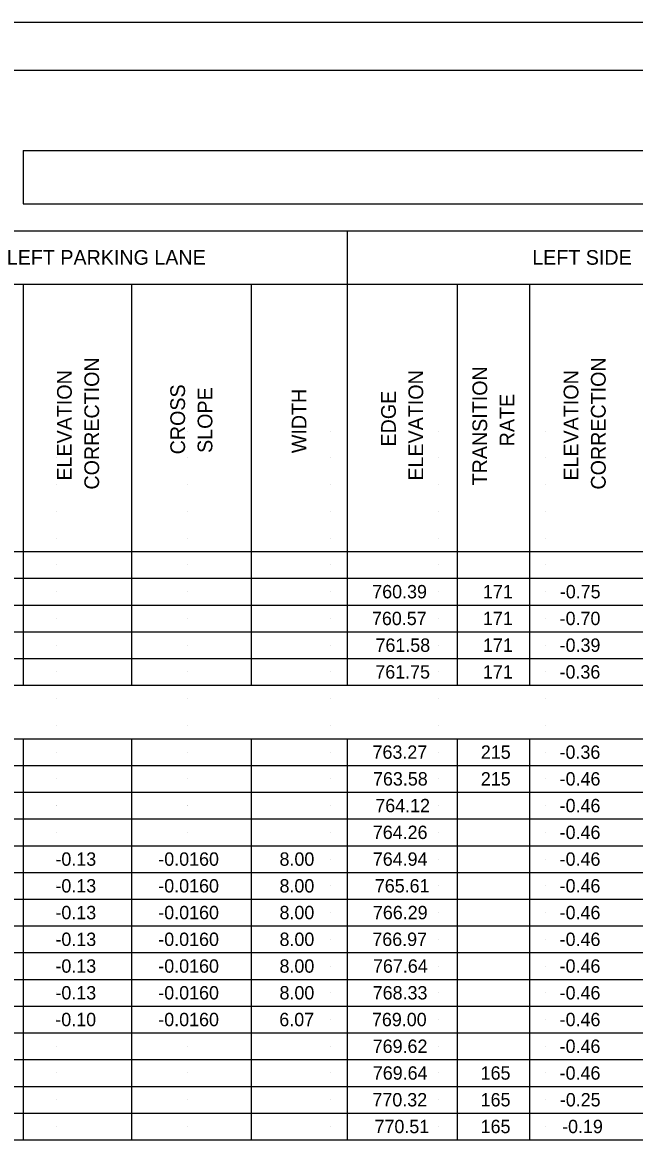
# Model space of a CAD drawing. Extents: x -15.4 to 18.6, y -12.6 to 9.4.
# Drawn here: x -8.91 to -2.5, y -2.38 to 9.39 of the extents above; entities that cross this region are included whole.
import ezdxf

# ---------------------------------------------------------------- set-up
doc = ezdxf.new("R2010")
doc.units = 0
for name, color, linetype in [('SH_Border', 7, 'Continuous'), ('SH_Cut_Line', 7, 'Continuous'), ('SH_Data', 7, 'Continuous'), ('SH_Text', 7, 'Continuous')]:
    doc.layers.add(name, color=color, linetype=linetype)

msp = doc.modelspace()

# ---------------------------------------------------------------- linework, layer by layer
at = {"layer": 'SH_Border'}
msp.add_lwpolyline([(-13.357, 8.888), (18.143, 8.888), (18.143, -12.112), (-13.357, -12.112)], close=True, dxfattribs=at)
at = {"layer": 'SH_Cut_Line'}
msp.add_lwpolyline([(-15.357, -12.612), (18.643, -12.612), (18.643, 9.388), (-15.357, 9.388)], close=True, dxfattribs=at)
at = {"layer": 'SH_Data'}
for p, q in [((-10.059, 8.888), (13.939, 8.888)), ((-8.906, 8.048), (12.061, 8.048)), ((-8.906, 8.048), (-8.906, 7.488)), ((-8.906, 7.488), (12.061, 7.488)), ((-10.059, 7.208), (13.939, 7.208)), ((-5.513, 7.208), (-5.513, 2.448)), ((-10.059, 6.648), (12.637, 6.648)), ((-8.906, 6.648), (-8.906, 2.448)), ((-7.77, 6.648), (-7.77, 2.448)), ((-6.518, 6.648), (-6.518, 2.448)), ((-4.36, 6.648), (-4.36, 2.448)), ((-3.603, 6.648), (-3.603, 2.448)), ((-8.557, 5.108), (-8.557, 5.108)), ((-7.182, 5.108), (-7.182, 5.108)), ((-5.682, 5.108), (-5.682, 5.108)), ((-4.557, 5.108), (-4.557, 5.108)), ((-3.432, 5.108), (-3.432, 5.108)), ((-8.557, 4.828), (-8.557, 4.828)), ((-7.182, 4.828), (-7.182, 4.828)), ((-5.682, 4.828), (-5.682, 4.828)), ((-4.557, 4.828), (-4.557, 4.828)), ((-3.432, 4.828), (-3.432, 4.828)), ((-8.557, 4.548), (-8.557, 4.548)), ((-7.182, 4.548), (-7.182, 4.548)), ((-5.682, 4.548), (-5.682, 4.548)), ((-4.557, 4.548), (-4.557, 4.548)), ((-3.432, 4.548), (-3.432, 4.548)), ((-8.557, 4.268), (-8.557, 4.268)), ((-7.182, 4.268), (-7.182, 4.268)), ((-5.682, 4.268), (-5.682, 4.268)), ((-4.557, 4.268), (-4.557, 4.268)), ((-3.432, 4.268), (-3.432, 4.268)), ((-8.557, 3.988), (-8.557, 3.988)), ((-7.182, 3.988), (-7.182, 3.988)), ((-5.682, 3.988), (-5.682, 3.988)), ((-4.557, 3.988), (-4.557, 3.988)), ((-3.432, 3.988), (-3.432, 3.988)), ((-10.059, 3.848), (13.939, 3.848)), ((-8.557, 3.708), (-8.557, 3.708)), ((-7.182, 3.708), (-7.182, 3.708)), ((-5.682, 3.708), (-5.682, 3.708)), ((-4.557, 3.708), (-4.557, 3.708)), ((-3.432, 3.708), (-3.432, 3.708)), ((-10.059, 3.568), (13.939, 3.568)), ((-8.557, 3.428), (-8.557, 3.428)), ((-7.182, 3.428), (-7.182, 3.428)), ((-5.682, 3.428), (-5.682, 3.428)), ((-4.557, 3.428), (-4.557, 3.428)), ((-3.432, 3.428), (-3.432, 3.428)), ((-10.059, 3.288), (13.939, 3.288)), ((-8.557, 3.148), (-8.557, 3.148)), ((-7.182, 3.148), (-7.182, 3.148)), ((-5.682, 3.148), (-5.682, 3.148)), ((-4.557, 3.148), (-4.557, 3.148)), ((-3.432, 3.148), (-3.432, 3.148)), ((-10.059, 3.008), (13.939, 3.008)), ((-8.557, 2.868), (-8.557, 2.868)), ((-7.182, 2.868), (-7.182, 2.868)), ((-5.682, 2.868), (-5.682, 2.868)), ((-4.557, 2.868), (-4.557, 2.868)), ((-3.432, 2.868), (-3.432, 2.868)), ((-10.059, 2.728), (13.939, 2.728)), ((-8.557, 2.588), (-8.557, 2.588)), ((-7.182, 2.588), (-7.182, 2.588)), ((-5.682, 2.588), (-5.682, 2.588)), ((-4.557, 2.588), (-4.557, 2.588)), ((-3.432, 2.588), (-3.432, 2.588)), ((-10.059, 2.448), (13.939, 2.448)), ((-8.557, 2.308), (-8.557, 2.308)), ((-7.182, 2.308), (-7.182, 2.308)), ((-5.682, 2.308), (-5.682, 2.308)), ((-4.557, 2.308), (-4.557, 2.308)), ((-3.432, 2.308), (-3.432, 2.308)), ((-8.557, 2.028), (-8.557, 2.028)), ((-7.182, 2.028), (-7.182, 2.028)), ((-5.682, 2.028), (-5.682, 2.028)), ((-4.557, 2.028), (-4.557, 2.028)), ((-3.432, 2.028), (-3.432, 2.028)), ((-10.059, 1.888), (13.939, 1.888)), ((-8.906, 1.888), (-8.906, -2.312)), ((-7.77, 1.888), (-7.77, -2.312)), ((-6.518, 1.888), (-6.518, -2.312)), ((-5.513, 1.888), (-5.513, -2.312)), ((-4.36, 1.888), (-4.36, -2.312)), ((-3.603, 1.888), (-3.603, -2.312)), ((-8.557, 1.748), (-8.557, 1.748)), ((-8.557, 1.748), (-8.557, 1.748)), ((-7.182, 1.748), (-7.182, 1.748)), ((-7.182, 1.748), (-7.182, 1.748)), ((-5.682, 1.748), (-5.682, 1.748)), ((-5.682, 1.748), (-5.682, 1.748)), ((-4.557, 1.748), (-4.557, 1.748)), ((-3.432, 1.748), (-3.432, 1.748)), ((-10.059, 1.608), (13.939, 1.608)), ((-8.557, 1.468), (-8.557, 1.468)), ((-8.557, 1.468), (-8.557, 1.468)), ((-7.182, 1.468), (-7.182, 1.468)), ((-7.182, 1.468), (-7.182, 1.468)), ((-5.682, 1.468), (-5.682, 1.468)), ((-5.682, 1.468), (-5.682, 1.468)), ((-4.557, 1.468), (-4.557, 1.468)), ((-3.432, 1.468), (-3.432, 1.468)), ((-10.059, 1.328), (13.939, 1.328)), ((-8.56, 1.188), (-8.56, 1.188)), ((-8.56, 1.188), (-8.56, 1.188)), ((-8.557, 1.188), (-8.557, 1.188)), ((-7.185, 1.188), (-7.185, 1.188)), ((-7.185, 1.188), (-7.185, 1.188)), ((-7.182, 1.188), (-7.182, 1.188)), ((-5.685, 1.188), (-5.685, 1.188)), ((-5.685, 1.188), (-5.685, 1.188)), ((-5.682, 1.188), (-5.682, 1.188)), ((-4.557, 1.188), (-4.557, 1.188)), ((-3.432, 1.188), (-3.432, 1.188)), ((-10.059, 1.048), (13.939, 1.048)), ((-8.557, 0.908), (-8.557, 0.908)), ((-7.182, 0.908), (-7.182, 0.908)), ((-5.682, 0.908), (-5.682, 0.908)), ((-4.557, 0.908), (-4.557, 0.908)), ((-3.432, 0.908), (-3.432, 0.908)), ((-10.059, 0.768), (13.939, 0.768)), ((-8.557, 0.628), (-8.557, 0.628)), ((-7.182, 0.628), (-7.182, 0.628)), ((-5.682, 0.628), (-5.682, 0.628)), ((-4.557, 0.628), (-4.557, 0.628)), ((-3.432, 0.628), (-3.432, 0.628)), ((-10.059, 0.488), (13.939, 0.488)), ((-8.557, 0.348), (-8.557, 0.348)), ((-7.182, 0.348), (-7.182, 0.348)), ((-5.682, 0.348), (-5.682, 0.348)), ((-4.557, 0.348), (-4.557, 0.348)), ((-3.432, 0.348), (-3.432, 0.348)), ((-10.059, 0.208), (13.939, 0.208)), ((-8.557, 0.068), (-8.557, 0.068)), ((-7.182, 0.068), (-7.182, 0.068)), ((-5.682, 0.068), (-5.682, 0.068)), ((-4.557, 0.068), (-4.557, 0.068)), ((-3.432, 0.068), (-3.432, 0.068)), ((-10.059, -0.072), (13.939, -0.072)), ((-8.557, -0.212), (-8.557, -0.212)), ((-7.182, -0.212), (-7.182, -0.212)), ((-5.682, -0.212), (-5.682, -0.212)), ((-4.557, -0.212), (-4.557, -0.212)), ((-3.432, -0.212), (-3.432, -0.212)), ((-10.059, -0.352), (13.939, -0.352)), ((-8.557, -0.492), (-8.557, -0.492)), ((-7.182, -0.492), (-7.182, -0.492)), ((-5.682, -0.492), (-5.682, -0.492)), ((-4.557, -0.492), (-4.557, -0.492)), ((-3.432, -0.492), (-3.432, -0.492)), ((-10.059, -0.632), (13.939, -0.632)), ((-8.557, -0.772), (-8.557, -0.772)), ((-7.182, -0.772), (-7.182, -0.772)), ((-5.682, -0.772), (-5.682, -0.772)), ((-4.557, -0.772), (-4.557, -0.772)), ((-3.432, -0.772), (-3.432, -0.772)), ((-10.059, -0.912), (13.939, -0.912)), ((-8.557, -1.052), (-8.557, -1.052)), ((-7.182, -1.052), (-7.182, -1.052)), ((-5.682, -1.052), (-5.682, -1.052)), ((-4.557, -1.052), (-4.557, -1.052)), ((-3.432, -1.052), (-3.432, -1.052)), ((-10.059, -1.192), (13.939, -1.192)), ((-8.557, -1.332), (-8.557, -1.332)), ((-7.182, -1.332), (-7.182, -1.332)), ((-5.682, -1.332), (-5.682, -1.332)), ((-4.557, -1.332), (-4.557, -1.332)), ((-3.432, -1.332), (-3.432, -1.332)), ((-10.059, -1.472), (13.939, -1.472)), ((-8.557, -1.612), (-8.557, -1.612)), ((-7.182, -1.612), (-7.182, -1.612)), ((-5.682, -1.612), (-5.682, -1.612)), ((-4.557, -1.612), (-4.557, -1.612)), ((-3.432, -1.612), (-3.432, -1.612)), ((-10.059, -1.752), (13.939, -1.752)), ((-8.557, -1.892), (-8.557, -1.892)), ((-7.182, -1.892), (-7.182, -1.892)), ((-5.682, -1.892), (-5.682, -1.892)), ((-4.557, -1.892), (-4.557, -1.892)), ((-3.432, -1.892), (-3.432, -1.892)), ((-10.059, -2.032), (13.939, -2.032)), ((-8.557, -2.172), (-8.557, -2.172)), ((-7.182, -2.172), (-7.182, -2.172)), ((-5.682, -2.172), (-5.682, -2.172)), ((-4.557, -2.172), (-4.557, -2.172)), ((-3.432, -2.172), (-3.432, -2.172)), ((-10.059, -2.312), (13.939, -2.312))]:
    msp.add_line(p, q, dxfattribs=at)

# ---------------------------------------------------------------- texts
at = {"layer": 'SH_Text'}
for s, height, p in [('LEFT PARKING LANE', 0.154, (-9.076, 6.851)), ('LEFT SIDE ', 0.154, (-3.575, 6.851)), ('760.39', 0.14, (-5.25, 3.358)), ('171', 0.14, (-4.091, 3.358)), ('-0.75', 0.14, (-3.286, 3.358)), ('760.57', 0.14, (-5.253, 3.078)), ('171', 0.14, (-4.091, 3.078)), ('-0.70', 0.14, (-3.288, 3.078)), ('761.58', 0.14, (-5.216, 2.798)), ('171', 0.14, (-4.091, 2.798)), ('-0.39', 0.14, (-3.288, 2.798)), ('761.75', 0.14, (-5.218, 2.518)), ('171', 0.14, (-4.091, 2.518)), ('-0.36', 0.14, (-3.289, 2.518)), ('763.27', 0.14, (-5.247, 1.678)), ('215', 0.14, (-4.113, 1.678)), ('-0.36', 0.14, (-3.289, 1.678)), ('763.58', 0.14, (-5.242, 1.398)), ('215', 0.14, (-4.113, 1.398)), ('-0.46', 0.14, (-3.288, 1.398)), ('764.12', 0.14, (-5.218, 1.118)), ('-0.46', 0.14, (-3.288, 1.118)), ('764.26', 0.14, (-5.244, 0.838)), ('-0.46', 0.14, (-3.288, 0.838)), ('-0.13', 0.14, (-8.567, 0.558)), ('-0.0160', 0.14, (-7.49, 0.558)), ('8.00', 0.14, (-6.221, 0.558)), ('764.94', 0.14, (-5.244, 0.558)), ('-0.46', 0.14, (-3.288, 0.558)), ('-0.13', 0.14, (-8.567, 0.278)), ('-0.0160', 0.14, (-7.49, 0.278)), ('8.00', 0.14, (-6.221, 0.278)), ('765.61', 0.14, (-5.223, 0.278)), ('-0.46', 0.14, (-3.288, 0.278)), ('-0.13', 0.14, (-8.567, -0.002)), ('-0.0160', 0.14, (-7.49, -0.002)), ('8.00', 0.14, (-6.221, -0.002)), ('766.29', 0.14, (-5.243, -0.002)), ('-0.46', 0.14, (-3.288, -0.002)), ('-0.13', 0.14, (-8.567, -0.282)), ('-0.0160', 0.14, (-7.49, -0.282)), ('8.00', 0.14, (-6.221, -0.282)), ('766.97', 0.14, (-5.249, -0.282)), ('-0.46', 0.14, (-3.288, -0.282)), ('-0.13', 0.14, (-8.567, -0.562)), ('-0.0160', 0.14, (-7.49, -0.562)), ('8.00', 0.14, (-6.221, -0.562)), ('767.64', 0.14, (-5.242, -0.562)), ('-0.46', 0.14, (-3.288, -0.562)), ('-0.13', 0.14, (-8.567, -0.842)), ('-0.0160', 0.14, (-7.49, -0.842)), ('8.00', 0.14, (-6.221, -0.842)), ('768.33', 0.14, (-5.245, -0.842)), ('-0.46', 0.14, (-3.288, -0.842)), ('-0.10', 0.14, (-8.568, -1.122)), ('-0.0160', 0.14, (-7.49, -1.122)), ('6.07', 0.14, (-6.223, -1.122)), ('769.00', 0.14, (-5.253, -1.122)), ('-0.46', 0.14, (-3.288, -1.122)), ('769.62', 0.14, (-5.245, -1.402)), ('-0.46', 0.14, (-3.288, -1.402)), ('769.64', 0.14, (-5.244, -1.682)), ('165', 0.14, (-4.115, -1.682)), ('-0.46', 0.14, (-3.288, -1.682)), ('770.32', 0.14, (-5.248, -1.962)), ('165', 0.14, (-4.115, -1.962)), ('-0.25', 0.14, (-3.286, -1.962)), ('770.51', 0.14, (-5.226, -2.242)), ('165', 0.14, (-4.115, -2.242)), ('-0.19', 0.14, (-3.262, -2.242))]:
    msp.add_text(s, height=height, dxfattribs=at).set_placement(p)
for s, p in [('CORRECTION', (-8.11, 4.497)), ('TRANSITION', (-4.047, 4.541)), ('CORRECTION', (-2.806, 4.497)), ('ELEVATION', (-8.396, 4.591)), ('ELEVATION', (-4.717, 4.591)), ('ELEVATION', (-3.092, 4.591)), ('CROSS', (-7.21, 4.866)), ('SLOPE', (-6.924, 4.881)), ('WIDTH', (-5.939, 4.878)), ('EDGE', (-5.003, 4.948)), ('RATE', (-3.762, 4.95))]:
    msp.add_text(s, height=0.154, rotation=90, dxfattribs=at).set_placement(p)

doc.saveas('drawing.dxf')
